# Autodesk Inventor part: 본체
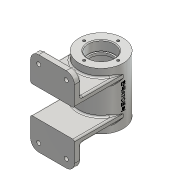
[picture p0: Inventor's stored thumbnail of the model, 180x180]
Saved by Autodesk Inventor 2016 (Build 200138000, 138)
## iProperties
Created: 2017-02
Part Number: 본체
Material: 알루미늄 6061
Document SubType Name: Modeling
Designer: H
Density: 2.7 g/cm^3
Appearance: 알루미늄 - 평지
Mass: 354.768 g
Surface Area: 422.768 cm^2
Volume: 131.396 cm^3
Author: H
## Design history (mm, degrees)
sketch "스케치1"
  geometry: C1 r 27 at (0, 0) reference
  constraints: 1 centre point, 2 other
  dimensions: "d1" = 54 diameter of C1 (derived)
extrude "돌출1" new body sketch "스케치1" stored distance "d2" = 70; taper "d3" = 0 deg
sketch "스케치4"
  geometry: L1 (0, 0)-(-60, 0); L2 (-52, 52)-(-60, 52); L3 (-52, -52)-(-60, -52); L4 (-52, 17)-(-60, 17); L5 (-52, -17)-(-60, -17); L6 (-52, 52)-(-52, 17); L7 (-52, -17)-(-52, -52); L8 (-60, 52)-(-60, 17); L9 (-60, -17)-(-60, -52)
  constraints: 18 end point, 4 parallel, 4 vertical, 1 horizontal
  dimensions: "d8" = 60 distance of L1.start L1.end; "d9" = 52 distance between parallel lines of L1 L2; "d10" = 104 distance between parallel lines of L2 L3; "d15" = 17 distance between parallel lines of L1 L4; "d16" = 17 distance between parallel lines of L1 L5; "d17" = 60 distance from line of L1.start L8; "d18" = 60 distance from line of L1.start L9
extrude "돌출2" join sketch "스케치4" stored distance "d13" = 54; taper "d14" = 0 deg
sketch "스케치5"
  geometry: L1 (-60, 52)-(-52, 52) reference; L2 (-52, 52)-(-52, 17) reference; L3 (-52, 17)-(-60, 17) reference; L4 (-60, 17)-(-60, 52) reference; L5 (-52, -52)-(-60, -52) reference; L6 (-60, -52)-(-60, -17) reference; L7 (-60, -17)-(-52, -17) reference; L8 (-52, -17)-(-52, -52) reference; L9 (-60, 17)-(0, 17); L10 (-60, 25)-(0, 25); L11 (-60, -17)-(0, -17); L12 (-60, -25)-(0, -25); L13 (-60, 25)-(-60, 17); L14 (-60, -17)-(-60, -25); L15 (-27, -35)-(27, -35) reference; L16 (27, 35)-(-27, 35) reference; L17 (0, 25)-(0, 17); L18 (0, -17)-(0, -25); 1 further point
  constraints: 16 end point, 2 collinear, 2 horizontal, 2 parallel
  dimensions: "d19" = 8 distance between parallel lines of L9 L10; "d20" = 8 distance between parallel lines of L11 L12
extrude "돌출3" join sketch "스케치5" stored distance "d21" = 54; taper "d22" = 0 deg
sketch "스케치6"
  geometry: L1 (27, 35)-(-27, 35) reference; L2 (27, -35)-(27, 35) reference; L3 (32, 10)-(-27, 10); L4 (32, 15)-(13.126, 15); L5 (13.126, 15)-(13.126, 10); L6 (-60, 17)-(-60, 52) reference; L7 (32, 15)-(32, 10); L8 (32, 10)-(13.126, 10); 1 further point
  constraints: 10 end point, 2 parallel, 1 collinear, 1 perpendicular, 1 point on line, 1 vertical
  dimensions: "d23" = 25 distance between parallel lines of L1 L3; "d24" = 5 distance between parallel lines of L3 L4; "d26" = 92 distance between parallel lines of L7 L6
revolve "회전1" sketch "스케치6" stored, may be unused: angle "d27" = 90 deg
sketch "스케치8"
  geometry: C1 r 5 at (0, 0) reference; 1 further point
hole "구멍1" sketch "스케치8" at (0, 0) diameter "d38" = 5.188; stored, may be unused: countersink angle "d42" = 90 deg, drill point angle "d44" = 118 deg; dims "d39" = 30, "d40" = 4, "d41" = 2, "d43" = 34
sketch "스케치9"
  geometry: C1 r 27 at (0, 0) reference; A1 r 21 centre (0, 0) between (0, 21) and (21, 0); 2 further points
  constraints: 4 point on circle, 1 centre point, 1 coincident
hole "구멍2" sketch "스케치9" at (0, 21), (21, 0), (0, -21), (-21, 0) diameter "d46" = 3.242; stored, may be unused: countersink angle "d50" = 90 deg, drill point angle "d52" = 118 deg; dims "d47" = 8, "d48" = 4, "d49" = 2, "d51" = 10
node "작업 평면1"
sketch "스케치10"
  geometry: L1 (0, 0)-(0, -40.315); L2 (0, 0)-(-16.339, -25.16); L3 (-11.307, -28.428)-(-1.668, -13.584); L4 (-11.307, -28.428)-(-16.339, -25.16); L5 (-1.668, -13.584)-(-6.7, -10.317); C1 r 27 at (0, 0) reference; 1 further point
  constraints: 10 end point, 1 point on line, 1 vertical
  dimensions: "d59" = 33 deg angle of L2 L1; "d60" = 30 distance of L1.start L2.end; "d62" = 12 diameter of L3 L2
revolve "회전5" stored, may be unused: angle "d63" = 90 deg
sketch "스케치7"
  geometry: L1 (27, 35)-(-27, 35) reference; L2 (-27, -35)-(27, -35) reference; L3 (0, 35)-(0, -35); L4 (0, 35)-(16, 35); L5 (16, 23)-(14, 23); L6 (14, 23)-(14, 20); L7 (16, 35)-(16, 23); L8 (14, 20)-(22, 20); L9 (22, 20)-(22, -20); L10 (22, -20)-(14, -20); L11 (14, -20)-(14, -23); L12 (14, -23)-(16, -23); L13 (16, -23)-(16, -35); L14 (16, -35)-(0, -35); 1 further point
  constraints: 24 end point, 6 perpendicular, 2 horizontal, 2 midpoint, 2 point on line, 1 collinear, 1 vertical
  dimensions: "d28" = 32 diameter of L7 L3; "d29" = 28 diameter of L6 L3; "d30" = 44 diameter of L9 L3; "d31" = 28 diameter of L11 L3; "d32" = 32 diameter of L13 L3; "d33" = 40 distance of L8.end L9.end; "d34" = 12 distance of L4.end L5.start; "d35" = 12 distance of L12.end L13.end; "d36" = 3 distance of L10.end L11.end
revolve "회전4" sketch "스케치7" stored, may be unused: angle "d58" = 90 deg
sketch "스케치11"
  geometry: 1 further point
hole "구멍3" sketch "스케치11" at (0, 0) diameter "d64" = 5.188; stored, may be unused: countersink angle "d68" = 90 deg, drill point angle "d70" = 118 deg; dims "d65" = 20, "d66" = 4, "d67" = 2, "d69" = 24
sketch "스케치12"
  geometry: L1 (0, 0)-(0, -35) reference; L2 (54, 0)-(0, 0) reference; L3 (54, -35)-(54, 0) reference; L4 (54, -35)-(0, -35) reference; L5 (54, -104)-(54, -69) reference; L6 (0, -104)-(54, -104) reference; L7 (0, -69)-(0, -104) reference; L8 (0, -69)-(54, -69) reference; L9 (27, -52)-(27, -126.559); L10 (27, -52)-(68.66, -52); L11 (27, -52)-(-16.754, -52); L12 (27, -52)-(27, 13.79); L13 (68.66, -10)-(27, -10); L14 (27, -10)-(-16.754, -10); L15 (68.66, -94)-(27, -94); L16 (27, -94)-(-16.754, -94); L17 (44, 13.79)-(44, -104); L18 (10, 13.79)-(10, -104); L19 (41.402, -14.5)-(38.804, -10); L20 (38.804, -10)-(41.402, -5.5); L21 (41.402, -5.5)-(46.598, -5.5); L22 (46.598, -5.5)-(49.196, -10); L23 (49.196, -10)-(46.598, -14.5); L24 (46.598, -14.5)-(41.402, -14.5); L25 (41.402, -98.5)-(38.804, -94); L26 (38.804, -94)-(41.402, -89.5); L27 (41.402, -89.5)-(46.598, -89.5); L28 (46.598, -89.5)-(49.196, -94); L29 (49.196, -94)-(46.598, -98.5); L30 (46.598, -98.5)-(41.402, -98.5); L31 (7.402, -98.5)-(4.804, -94); L32 (4.804, -94)-(7.402, -89.5); L33 (7.402, -89.5)-(12.598, -89.5); L34 (12.598, -89.5)-(15.196, -94); L35 (15.196, -94)-(12.598, -98.5); L36 (12.598, -98.5)-(7.402, -98.5); L37 (7.402, -14.5)-(4.804, -10); L38 (4.804, -10)-(7.402, -5.5); L39 (7.402, -5.5)-(12.598, -5.5); L40 (12.598, -5.5)-(15.196, -10); L41 (15.196, -10)-(12.598, -14.5); L42 (12.598, -14.5)-(7.402, -14.5); 9 further points
  constraints: 68 end point, 7 point on line, 4 midpoint, 2 horizontal, 2 vertical, 1 parallel, 54 other
  dimensions: "d71" = 42 distance between parallel lines of L10 L13; "d72" = 42 distance between parallel lines of L10 L15; "d73" = 17 distance between parallel lines of L12 L17; "d74" = 34 distance between parallel lines of L17 L18
extrude "돌출4" cut sketch "스케치12" distance "d79" = 3; taper "d80" = 0 deg
sketch "스케치13"
  geometry: L1 (49.774, -10)-(4.226, -10); L2 (49.774, -94)-(4.226, -94); L3 (44, -5)-(44, -99); L4 (10, -5)-(10, -99); 9 further points
  constraints: 8 end point, 8 point on line, 4 coincident, 2 horizontal
hole "구멍4" sketch "스케치13" at (44, -10), (44, -94), (10, -94), (10, -10) diameter "d81" = 5; stored, may be unused: countersink angle "d85" = 90 deg, drill point angle "d87" = 118 deg; dims "d82" = 20, "d83" = 4, "d84" = 2, "d86" = 24
chamfer "모따기1" distance "d88" = 1; stored, may be unused: second distance "d89" = 2, angle "d90" = 45 deg
fillet "모깎기1" dims "d91" = 2
fillet "모깎기2" dims "d92" = 2
fillet "모깎기3" dims "d93" = 2
fillet "모깎기4" dims "d100" = 10
fillet "모깎기5" dims "d101" = 2
fillet "모깎기6" dims "d102" = 2
fillet "모깎기7" dims "d103" = 3
fillet "모깎기8" dims "d104" = 0.3
node "작업 평면2"
sketch "스케치14"
  geometry: L1 (27, 35)-(-27, 35) reference; L2 (2.402, 7.767)-(2.402, -7.767); L3 (2.402, -7.767)-(-2.402, -7.767); L4 (-2.402, -7.767)-(-2.402, 7.767); L5 (-2.402, 7.767)-(2.402, 7.767); L6 (0, 35)-(0, -39.597); L7 (0, 0)-(39.539, 0); L8 (27, -35)-(27, 35) reference; L9 (-27, -35)-(-27, 35) reference; 2 further points
  constraints: 4 end point, 3 midpoint, 1 horizontal, 1 horizontal alignment, 1 vertical, 1 vertical alignment, 2 other
feature "엠보싱1" sketch "스케치14" dims "d3" = 0, "d106" = 0.5, "d107" = 0
node "솔리드1"
mirror "대칭1"
node "투영된 루프2"
node "투영된 루프3"
node "투영된 루프4"
node "투영된 루프5"
node "투영된 루프8"
node "투영된 루프9"
other parameters: "d11" = 8, "d55" = 6, "d105" = 41
